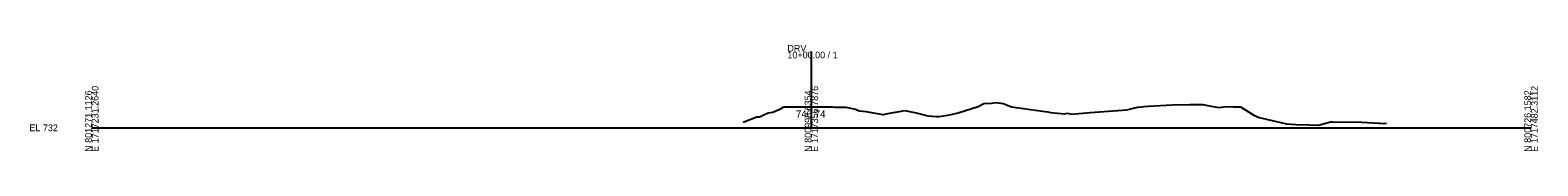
# Model space of a CAD drawing. Extents: x -26 to 603, y -10 to 3134.
# Drawn here: x -26 to 603, y -10 to 35 of the extents above; entities that cross this region are included whole.
import ezdxf

# ---------------------------------------------------------------- set-up
doc = ezdxf.new("R2010")
doc.units = 0
for name, color, linetype in [('Exist Cross Section Cell', 7, 'Continuous'), ('Exist XS Center Line Elevation Label', 7, 'Continuous'), ('Exist XS Ground Line', 7, 'Continuous')]:
    doc.layers.add(name, color=color, linetype=linetype)

msp = doc.modelspace()

# ---------------------------------------------------------------- linework, layer by layer
at = {"layer": 'Exist Cross Section Cell'}
for p, q in [((300, 0), (300, 31.76)), ((0, 0), (300, 0)), ((300, 0), (600, 0))]:
    msp.add_line(p, q, dxfattribs=at)
at = {"layer": 'Exist XS Ground Line'}
for p, q in [((282.01, 6.21), (283.87, 6.53)), ((283.87, 6.53), (287.38, 8.05)), ((287.38, 8.05), (288.52, 8.77)), ((288.52, 8.77), (289.37, 8.81)), ((289.37, 8.81), (291.14, 8.78)), ((291.14, 8.78), (300, 8.74)), ((300, 8.74), (305.44, 8.71)), ((305.44, 8.71), (308.83, 8.73)), ((308.83, 8.73), (309.7, 8.67)), ((309.7, 8.67), (314.3, 8.63)), ((314.3, 8.63), (318.35, 7.74)), ((318.35, 7.74), (319.97, 7.15)), ((319.97, 7.15), (321.52, 6.91)), ((321.52, 6.91), (322.7, 6.8)), ((322.7, 6.8), (329.8, 5.58)), ((331.18, 5.86), (338.92, 7.19)), ((338.92, 7.19), (343.64, 6.24)), ((361.23, 6.21), (369.46, 8.86)), ((369.46, 8.86), (371.89, 10.21)), ((371.89, 10.21), (375.12, 10.33)), ((375.12, 10.33), (377.06, 10.59)), ((377.06, 10.59), (379.89, 10.14)), ((379.89, 10.14), (382.75, 8.98)), ((382.75, 8.98), (383.47, 8.78)), ((383.47, 8.78), (395.32, 7.14)), ((395.32, 7.14), (396.46, 7.01)), ((396.46, 7.01), (397.25, 6.86)), ((397.25, 6.86), (398.52, 6.63)), ((398.52, 6.63), (399.62, 6.45)), ((399.62, 6.45), (405.51, 5.81)), ((408.37, 5.76), (416.19, 6.39)), ((416.19, 6.39), (427.74, 7.24)), ((427.74, 7.24), (431.5, 7.49)), ((431.5, 7.49), (431.53, 7.49)), ((431.53, 7.49), (431.55, 7.49)), ((431.55, 7.49), (435.45, 8.42)), ((435.45, 8.42), (436.15, 8.65)), ((436.15, 8.65), (437.77, 8.79)), ((437.77, 8.79), (438.63, 8.87)), ((438.63, 8.87), (440.59, 8.99)), ((440.59, 8.99), (450.46, 9.62)), ((450.46, 9.62), (457.72, 9.68)), ((457.72, 9.68), (463.22, 9.7)), ((463.22, 9.7), (466.71, 9.02)), ((466.71, 9.02), (469.83, 8.54)), ((469.83, 8.54), (473.09, 8.84)), ((473.09, 8.84), (475.8, 8.74)), ((475.8, 8.74), (478.93, 8.71)), ((478.93, 8.71), (484.45, 5.25)), ((271.56, 2.36), (277.24, 4.52)), ((277.24, 4.52), (278.4, 4.52)), ((278.4, 4.52), (282.01, 6.21)), ((329.8, 5.58), (330.22, 5.6)), ((330.22, 5.6), (331.18, 5.86)), ((343.64, 6.24), (348.47, 5.04)), ((348.47, 5.04), (352.2, 4.74)), ((352.2, 4.74), (353.31, 4.73)), ((353.31, 4.73), (357.77, 5.46)), ((357.77, 5.46), (361.23, 6.21)), ((405.51, 5.81), (406.71, 6.18)), ((406.71, 6.18), (408.37, 5.76)), ((484.45, 5.25), (486.69, 4.25)), ((486.69, 4.25), (487.87, 4.03)), ((487.87, 4.03), (498, 1.66)), ((498, 1.66), (501.98, 1.36)), ((501.98, 1.36), (507.47, 1.23)), ((507.47, 1.23), (511.39, 1.17)), ((511.39, 1.17), (516.36, 2.47)), ((516.36, 2.47), (517.11, 2.5)), ((517.11, 2.5), (529.46, 2.42)), ((529.46, 2.42), (536.52, 1.96)), ((536.52, 1.96), (537.29, 1.95)), ((537.29, 1.95), (538.36, 1.76)), ((538.36, 1.76), (539.68, 1.99))]:
    msp.add_line(p, q, dxfattribs=at)

# ---------------------------------------------------------------- texts
at = {"layer": 'Exist Cross Section Cell'}
for s, p in [('10+00.00 / 1', (290, 28.96)), ('DRV', (290, 31.76)), ('EL 732', (-26, -1.4))]:
    msp.add_text(s, height=2.8, dxfattribs=at).set_placement(p)
for s, p in [('N 801271.1126', (0, -10)), ('E 1717231.2640', (2.8, -10)), ('N 800998.6354', (300, -10)), ('E 1717356.7876', (302.8, -10)), ('N 800726.1582', (600, -10)), ('E 1717482.3112', (602.8, -10))]:
    msp.add_text(s, height=2.8, rotation=90, dxfattribs=at).set_placement(p)
at = {"layer": 'Exist XS Center Line Elevation Label'}
msp.add_text('740.74', height=3, dxfattribs=at).set_placement((293.57, 4.24))

doc.saveas('drawing.dxf')
